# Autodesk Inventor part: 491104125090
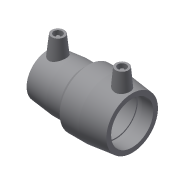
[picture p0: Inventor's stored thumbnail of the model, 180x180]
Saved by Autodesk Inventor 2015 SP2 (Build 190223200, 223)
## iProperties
Created: 2017-06
Part Number: 491104125090
Material: Generic
Description: PLASSON REDUCING COUPLER 125-90
Document SubType Name: Modeling
Designer: KIM
Mass: 54.8237 g
Surface Area: 155.252 cm^2
Volume: 54.8237 cm^3
Density: 1 g/cm^3
Appearance: Default
Author: KIM
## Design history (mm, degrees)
derived "491104.ipt"
feature "Solid1::491104.ipt"
tag "TaggingFeature1"
body "Solid1"
other parameters: "L_" = 171, "L_2" = 72, "D_1" = 116, "d_2" = 12, "L_1" = 85, "d_" = 125, "A_" = 88, "D_" = 158, "d0" = 171, "d2" = 116, "d3" = 72, "d4" = 43.2, "d5" = 104.4, "d8" = 168 deg, "d10" = 28.8, "d11" = 9.6, "d13" = 171, "d14" = 17.6296, "d15" = 72, "d19" = 3.6, "d20" = 168 deg, "d22" = 108.92847, "d25" = 135 deg, "d30" = 15, "d31" = 59.85, "d34" = 6 deg, "d35" = 15, "d38" = 20.5, "d39" = 5 deg, "d41" = 4, "d42" = 14, "d43" = 0, "d45" = 4, "d46" = 14, "d47" = 0, "d48" = 116, "d49" = 125, "d50" = 158, "d52" = 81, "d53" = 34, "d54" = 11.33333, "d55" = 168 deg, "d56" = 51, "d57" = 85, "d58" = 142.2, "d59" = 3.6, "d60" = 135 deg, "d61" = 88, "d62" = 15, "d64" = 4, "d66" = 5 deg, "d67" = 14, "d68" = 0, "d69" = 59.85, "d70" = 116, "d71" = 158, "d73" = 148.52, "d76" = 3.6, "d77" = 168 deg, "d78" = 125, "d79" = 3.6, "d80" = 85, "d81" = 81, "d82" = 109.04, "d83" = 120 deg, "d88" = 15, "d89" = 19.25, "d90" = 5 deg, "d92" = 4, "d93" = 14, "d94" = 0, "d95" = 3, "d96" = 0, "d97" = 3, "d98" = 0, "d99" = 20.88, "d100" = 5.22, "d101" = 105.7688, "d102" = 20 deg, "d103" = 24.65, "d104" = 6.1625, "d105" = 144.0644, "d106" = 3.60705, "d107" = 3, "d108" = 0, "d109" = 3, "d110" = 0
